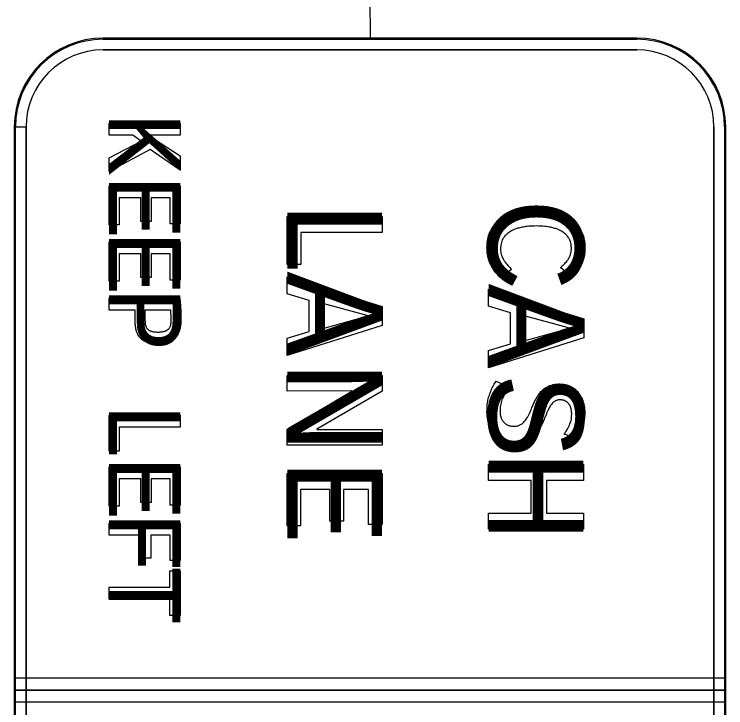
# Model space of a CAD drawing. Extents: x 46672 to 47298, y 5424 to 5829.
# Drawn here: x 46761.54 to 46786.99, y 5574.03 to 5598.84 of the extents above; entities that cross this region are included whole.
import ezdxf

# ---------------------------------------------------------------- set-up
doc = ezdxf.new("R2010")
doc.units = 0
doc.layers.add('LeaderLine_dp', color=7, linetype='Continuous')
doc.layers.add('SignPanel', color=7, linetype='Continuous')

msp = doc.modelspace()

# ---------------------------------------------------------------- linework, layer by layer
at = {"layer": 'LeaderLine_dp'}
msp.add_line((46774.261, 5605.249), (46774.267, 5597.985), dxfattribs=at)
at = {"layer": 'SignPanel'}
for p, q in [((46783.809, 5597.985), (46764.724, 5597.985)), ((46783.809, 5597.985), (46764.724, 5597.985)), ((46783.809, 5597.985), (46764.724, 5597.985)), ((46783.809, 5597.985), (46764.724, 5597.985)), ((46764.724, 5597.943), (46783.809, 5597.943)), ((46783.809, 5597.561), (46764.724, 5597.561)), ((46764.724, 5597.561), (46783.809, 5597.561)), ((46764.724, 5597.561), (46783.809, 5597.561)), ((46761.543, 5594.805), (46761.543, 5552.818)), ((46761.543, 5594.805), (46761.543, 5552.818)), ((46761.543, 5594.805), (46761.968, 5594.805)), ((46761.543, 5594.805), (46761.968, 5594.805)), ((46761.543, 5594.805), (46761.586, 5594.805)), ((46761.543, 5594.804), (46761.543, 5552.818)), ((46761.586, 5594.804), (46761.543, 5594.804)), ((46761.543, 5594.8), (46761.543, 5552.818)), ((46761.968, 5594.8), (46761.543, 5594.8)), ((46761.543, 5594.8), (46761.543, 5552.818)), ((46761.968, 5594.8), (46761.543, 5594.8)), ((46761.586, 5552.818), (46761.586, 5594.804)), ((46761.968, 5594.805), (46761.968, 5552.818)), ((46761.968, 5552.818), (46761.968, 5594.8)), ((46761.968, 5552.818), (46761.968, 5594.8)), ((46786.566, 5552.818), (46786.566, 5594.805)), ((46786.566, 5594.805), (46786.566, 5552.818)), ((46786.566, 5594.805), (46786.566, 5552.818)), ((46786.947, 5594.805), (46786.947, 5552.818)), ((46786.99, 5552.818), (46786.99, 5594.805)), ((46786.99, 5552.818), (46786.99, 5594.805)), ((46786.99, 5552.818), (46786.99, 5594.805)), ((46786.99, 5552.818), (46786.99, 5594.805)), ((46786.99, 5552.818), (46786.99, 5594.805)), ((46761.543, 5575.084), (46761.543, 5574.659)), ((46786.99, 5575.084), (46761.543, 5575.084)), ((46761.543, 5575.084), (46761.543, 5574.659)), ((46786.99, 5575.084), (46761.543, 5575.084)), ((46761.543, 5575.084), (46761.543, 5574.659)), ((46786.99, 5575.084), (46761.543, 5575.084)), ((46786.99, 5574.659), (46786.99, 5575.084)), ((46786.99, 5574.659), (46786.99, 5575.084)), ((46786.99, 5574.659), (46786.99, 5575.084)), ((46761.543, 5574.659), (46786.99, 5574.659)), ((46761.543, 5574.659), (46786.99, 5574.659)), ((46761.543, 5574.659), (46786.99, 5574.659)), ((46761.543, 5574.659), (46761.543, 5574.235)), ((46786.99, 5574.659), (46761.543, 5574.659)), ((46761.543, 5574.659), (46761.543, 5574.235)), ((46786.99, 5574.659), (46761.543, 5574.659)), ((46761.543, 5574.659), (46761.543, 5574.235)), ((46786.99, 5574.659), (46761.543, 5574.659)), ((46786.99, 5574.235), (46786.99, 5574.659)), ((46786.99, 5574.235), (46786.99, 5574.659)), ((46786.99, 5574.235), (46786.99, 5574.659)), ((46761.543, 5574.235), (46786.99, 5574.235)), ((46761.543, 5574.235), (46786.99, 5574.235)), ((46761.543, 5574.235), (46786.99, 5574.235))]:
    msp.add_line(p, q, dxfattribs=at)
for points in [[(46764.936, 5593.706), (46766.084, 5594.294), (46765.786, 5594.516), (46764.936, 5594.513), (46764.936, 5594.943), (46767.481, 5594.943), (46767.481, 5594.513), (46766.356, 5594.516), (46766.356, 5594.5), (46767.481, 5593.774), (46767.481, 5593.264), (46766.399, 5593.994), (46764.936, 5593.215), (46764.936, 5593.706)], [(46764.936, 5592.704), (46767.481, 5592.704), (46767.481, 5591.337), (46767.116, 5591.337), (46767.116, 5592.274), (46766.445, 5592.274), (46766.445, 5591.427), (46766.077, 5591.427), (46766.077, 5592.274), (46765.295, 5592.274), (46765.295, 5591.303), (46764.936, 5591.303), (46764.936, 5592.704)], [(46771.306, 5591.598), (46774.699, 5591.598), (46774.699, 5591.025), (46771.793, 5591.025), (46771.793, 5589.883), (46771.306, 5589.883), (46771.306, 5591.598)], [(46764.936, 5590.691), (46767.481, 5590.691), (46767.481, 5589.324), (46767.116, 5589.324), (46767.116, 5590.261), (46766.445, 5590.261), (46766.445, 5589.414), (46766.077, 5589.414), (46766.077, 5590.261), (46765.295, 5590.261), (46765.295, 5589.29), (46764.936, 5589.29), (46764.936, 5590.691)], [(46779.333, 5589.71), (46778.937, 5589.408)], [(46781.478, 5589.428), (46781.081, 5589.774)], [(46771.306, 5587.245), (46772.094, 5587.482), (46772.094, 5588.601), (46771.306, 5588.832), (46771.306, 5589.439), (46774.707, 5588.387), (46774.707, 5587.699), (46771.306, 5586.628), (46771.306, 5587.245)], [(46778.508, 5586.804), (46779.295, 5587.041), (46779.295, 5588.16), (46778.508, 5588.391), (46778.508, 5588.998), (46781.909, 5587.946), (46781.909, 5587.258), (46778.508, 5586.187), (46778.508, 5586.804)], [(46765.87, 5587.848), (46765.87, 5588.248), (46764.936, 5588.248), (46764.936, 5588.678), (46767.465, 5588.678)], [(46774.168, 5588.035), (46774.168, 5588.055), (46772.58, 5588.493), (46772.58, 5587.594), (46774.168, 5588.035)], [(46767.138, 5588.248), (46766.219, 5588.248), (46766.219, 5587.912)], [(46781.37, 5587.594), (46781.37, 5587.614), (46779.782, 5588.052), (46779.782, 5587.153), (46781.37, 5587.594)], [(46771.306, 5583.978), (46773.62, 5585.35), (46773.62, 5585.361), (46771.306, 5585.355), (46771.306, 5585.915), (46774.699, 5585.915), (46774.699, 5585.35), (46772.365, 5583.99), (46772.365, 5583.978), (46774.699, 5583.978), (46774.699, 5583.425), (46771.306, 5583.425), (46771.306, 5583.978)], [(46778.78, 5585.711), (46779.248, 5585.501)], [(46764.936, 5584.49), (46767.481, 5584.49), (46767.481, 5584.06), (46765.301, 5584.06), (46765.301, 5583.203), (46764.936, 5583.203), (46764.936, 5584.49)], [(46781.682, 5583.649), (46781.207, 5583.816)], [(46778.508, 5580.99), (46780.029, 5580.99), (46780.029, 5582.153), (46778.508, 5582.153), (46778.508, 5582.726), (46781.901, 5582.726), (46781.901, 5582.153), (46780.573, 5582.153), (46780.573, 5580.99), (46781.901, 5580.99), (46781.901, 5580.417), (46778.508, 5580.417), (46778.508, 5580.99)], [(46764.936, 5582.642), (46767.481, 5582.642), (46767.481, 5581.276), (46767.116, 5581.276), (46767.116, 5582.212), (46766.445, 5582.212), (46766.445, 5581.365), (46766.077, 5581.365), (46766.077, 5582.212), (46765.295, 5582.212), (46765.295, 5581.242), (46764.936, 5581.242), (46764.936, 5582.642)], [(46771.306, 5582.407), (46774.699, 5582.407), (46774.699, 5580.585), (46774.213, 5580.585), (46774.213, 5581.834), (46773.318, 5581.834), (46773.318, 5580.704), (46772.827, 5580.704), (46772.827, 5581.834), (46771.784, 5581.834), (46771.784, 5580.539), (46771.306, 5580.539), (46771.306, 5582.407)], [(46767.116, 5580.2), (46766.433, 5580.2), (46766.433, 5579.377), (46766.065, 5579.377), (46766.065, 5580.2), (46764.936, 5580.2), (46764.936, 5580.629), (46767.481, 5580.629), (46767.481, 5579.291), (46767.116, 5579.291), (46767.116, 5580.2)], [(46767.11, 5577.912), (46764.936, 5577.912), (46764.936, 5578.341), (46767.11, 5578.341), (46767.11, 5578.929), (46767.481, 5578.929), (46767.481, 5577.322), (46767.11, 5577.322), (46767.11, 5577.912)]]:
    msp.add_lwpolyline(points, dxfattribs=at)
for centre, radius, start, end in [((46764.724, 5594.805), 3.181, 90, 180), ((46764.724, 5594.805), 3.181, 90, 180), ((46764.724, 5594.805), 3.181, 90, 180), ((46764.724, 5594.805), 3.181, 90, 180), ((46764.724, 5594.805), 3.181, 90, 180), ((46783.809, 5594.805), 3.181, 0, 90), ((46783.809, 5594.805), 3.181, 0, 90), ((46783.809, 5594.805), 3.181, 0, 90), ((46783.809, 5594.805), 3.181, 0, 90), ((46783.809, 5594.805), 3.181, 0, 90), ((46764.724, 5594.805), 3.138, 90, 180), ((46783.809, 5594.805), 3.138, 0, 90), ((46764.724, 5594.805), 2.757, 90, 180), ((46764.724, 5594.805), 2.757, 90, 180), ((46764.724, 5594.805), 2.757, 90, 180), ((46783.809, 5594.805), 2.757, 0, 90), ((46783.809, 5594.805), 2.757, 0, 90), ((46783.809, 5594.805), 2.757, 0, 90)]:
    msp.add_arc(centre, radius, start, end, dxfattribs=at)
for points in [[(46778.45, 5590.476), (46778.451, 5590.506), (46778.452, 5590.594), (46778.466, 5590.735), (46778.499, 5590.894), (46778.542, 5591.017), (46778.585, 5591.107), (46778.632, 5591.192), (46778.699, 5591.291), (46778.793, 5591.398), (46778.882, 5591.478), (46778.959, 5591.535), (46779.104, 5591.631), (46779.292, 5591.717), (46779.519, 5591.781), (46779.74, 5591.826), (46779.972, 5591.853), (46780.15, 5591.856), (46780.211, 5591.856)], [(46780.211, 5591.856), (46780.267, 5591.855), (46780.433, 5591.853), (46780.652, 5591.826), (46780.865, 5591.781), (46781.066, 5591.723), (46781.254, 5591.64), (46781.404, 5591.548), (46781.502, 5591.476), (46781.594, 5591.395), (46781.691, 5591.287), (46781.761, 5591.187), (46781.811, 5591.102), (46781.857, 5591.011), (46781.902, 5590.888), (46781.938, 5590.727), (46781.953, 5590.585), (46781.954, 5590.497), (46781.954, 5590.466)], [(46780.211, 5591.263), (46780.136, 5591.261), (46779.985, 5591.257), (46779.798, 5591.235), (46779.616, 5591.201), (46779.478, 5591.159), (46779.365, 5591.109), (46779.291, 5591.069), (46779.222, 5591.024), (46779.147, 5590.963), (46779.091, 5590.904), (46779.051, 5590.854), (46779.015, 5590.801), (46778.978, 5590.726), (46778.95, 5590.626), (46778.938, 5590.535), (46778.937, 5590.479), (46778.937, 5590.459)], [(46781.468, 5590.466), (46781.468, 5590.482), (46781.467, 5590.53), (46781.458, 5590.608), (46781.436, 5590.697), (46781.409, 5590.766), (46781.382, 5590.817), (46781.352, 5590.866), (46781.307, 5590.924), (46781.244, 5590.987), (46781.185, 5591.033), (46781.119, 5591.076), (46781.014, 5591.131), (46780.88, 5591.18), (46780.734, 5591.215), (46780.523, 5591.253), (46780.346, 5591.259), (46780.211, 5591.263)], [(46778.937, 5589.408), (46778.901, 5589.444), (46778.794, 5589.55), (46778.675, 5589.711), (46778.591, 5589.862), (46778.539, 5589.973), (46778.498, 5590.091), (46778.466, 5590.24), (46778.452, 5590.37), (46778.451, 5590.449), (46778.45, 5590.476)], [(46778.937, 5590.459), (46778.937, 5590.441), (46778.938, 5590.387), (46778.949, 5590.299), (46778.974, 5590.199), (46779.006, 5590.121), (46779.047, 5590.046), (46779.117, 5589.939), (46779.217, 5589.821), (46779.303, 5589.739), (46779.333, 5589.71)], [(46781.081, 5589.774), (46781.111, 5589.801), (46781.167, 5589.852), (46781.233, 5589.919), (46781.292, 5589.984), (46781.333, 5590.038), (46781.368, 5590.092), (46781.399, 5590.148), (46781.424, 5590.206), (46781.443, 5590.266), (46781.458, 5590.33), (46781.467, 5590.397), (46781.468, 5590.448), (46781.468, 5590.466)], [(46781.954, 5590.466), (46781.954, 5590.44), (46781.953, 5590.365), (46781.941, 5590.243), (46781.911, 5590.103), (46781.874, 5589.993), (46781.826, 5589.888), (46781.744, 5589.74), (46781.623, 5589.578), (46781.516, 5589.467), (46781.478, 5589.428)], [(46767.465, 5588.678), (46767.471, 5588.621), (46767.484, 5588.503), (46767.496, 5588.322), (46767.504, 5588.132), (46767.505, 5588.002), (46767.505, 5587.935)], [(46767.159, 5587.917), (46767.159, 5587.943), (46767.158, 5587.995), (46767.152, 5588.075), (46767.145, 5588.16), (46767.14, 5588.218), (46767.138, 5588.248)], [(46766.694, 5587.033), (46766.661, 5587.034), (46766.569, 5587.035), (46766.436, 5587.053), (46766.314, 5587.087), (46766.23, 5587.123), (46766.165, 5587.159), (46766.116, 5587.195), (46766.079, 5587.226), (46766.045, 5587.26), (46766.007, 5587.307), (46765.967, 5587.371), (46765.928, 5587.455), (46765.891, 5587.579), (46765.872, 5587.717), (46765.87, 5587.814), (46765.87, 5587.848)], [(46766.219, 5587.912), (46766.219, 5587.894), (46766.22, 5587.842), (46766.226, 5587.776), (46766.236, 5587.722), (46766.245, 5587.688), (46766.256, 5587.657), (46766.274, 5587.622), (46766.293, 5587.596), (46766.31, 5587.577), (46766.328, 5587.559), (46766.354, 5587.539), (46766.39, 5587.519), (46766.424, 5587.505), (46766.461, 5587.493), (46766.523, 5587.478), (46766.602, 5587.47), (46766.665, 5587.469), (46766.688, 5587.469)], [(46766.688, 5587.469), (46766.709, 5587.469), (46766.767, 5587.47), (46766.842, 5587.477), (46766.901, 5587.49), (46766.938, 5587.5), (46766.971, 5587.512), (46767.008, 5587.532), (46767.035, 5587.551), (46767.055, 5587.568), (46767.073, 5587.587), (46767.093, 5587.613), (46767.113, 5587.648), (46767.127, 5587.68), (46767.138, 5587.715), (46767.15, 5587.772), (46767.158, 5587.842), (46767.159, 5587.897), (46767.159, 5587.917)], [(46767.505, 5587.935), (46767.505, 5587.902), (46767.504, 5587.807), (46767.49, 5587.684), (46767.466, 5587.568), (46767.446, 5587.5), (46767.423, 5587.436), (46767.395, 5587.377), (46767.361, 5587.322), (46767.33, 5587.281), (46767.298, 5587.243), (46767.251, 5587.199), (46767.189, 5587.152), (46767.13, 5587.12), (46767.08, 5587.098), (46767.026, 5587.077), (46766.935, 5587.052), (46766.818, 5587.036), (46766.731, 5587.034), (46766.694, 5587.033)], [(46778.45, 5584.63), (46778.451, 5584.682), (46778.454, 5584.834), (46778.482, 5585.03), (46778.533, 5585.213), (46778.598, 5585.385), (46778.679, 5585.553), (46778.754, 5585.671), (46778.78, 5585.711)], [(46779.248, 5585.501), (46779.226, 5585.47), (46779.158, 5585.378), (46779.08, 5585.246), (46779.02, 5585.127), (46778.982, 5585.039), (46778.952, 5584.948), (46778.928, 5584.834), (46778.917, 5584.736), (46778.916, 5584.677), (46778.916, 5584.657)], [(46780.039, 5584.724), (46780.062, 5584.777), (46780.108, 5584.883), (46780.168, 5585.014), (46780.233, 5585.141), (46780.295, 5585.236), (46780.357, 5585.313), (46780.404, 5585.365), (46780.466, 5585.422), (46780.547, 5585.481), (46780.623, 5585.523), (46780.692, 5585.554), (46780.787, 5585.584), (46780.908, 5585.603), (46780.998, 5585.605), (46781.037, 5585.606)], [(46781.037, 5585.606), (46781.056, 5585.606), (46781.112, 5585.605), (46781.202, 5585.596), (46781.304, 5585.575), (46781.383, 5585.547), (46781.442, 5585.52), (46781.498, 5585.49), (46781.563, 5585.449), (46781.634, 5585.391), (46781.687, 5585.337), (46781.736, 5585.279), (46781.797, 5585.192), (46781.853, 5585.082), (46781.893, 5584.963), (46781.925, 5584.839), (46781.944, 5584.709), (46781.946, 5584.612), (46781.946, 5584.579)], [(46781.06, 5585.041), (46781.052, 5585.041), (46781.026, 5585.041), (46780.984, 5585.035), (46780.937, 5585.023), (46780.901, 5585.007), (46780.867, 5584.987), (46780.822, 5584.954), (46780.776, 5584.908), (46780.735, 5584.855), (46780.694, 5584.795), (46780.658, 5584.729), (46780.616, 5584.639), (46780.575, 5584.541), (46780.542, 5584.462), (46780.525, 5584.421)], [(46781.48, 5584.53), (46781.48, 5584.547), (46781.479, 5584.598), (46781.471, 5584.664), (46781.457, 5584.728), (46781.442, 5584.78), (46781.421, 5584.829), (46781.399, 5584.867), (46781.382, 5584.891), (46781.365, 5584.913), (46781.341, 5584.939), (46781.308, 5584.967), (46781.278, 5584.987), (46781.252, 5585.001), (46781.224, 5585.014), (46781.187, 5585.027), (46781.139, 5585.037), (46781.096, 5585.041), (46781.07, 5585.041), (46781.06, 5585.041)], [(46779.481, 5583.541), (46779.438, 5583.542), (46779.335, 5583.544), (46779.197, 5583.565), (46779.087, 5583.596), (46779.02, 5583.622), (46778.958, 5583.65), (46778.884, 5583.69), (46778.803, 5583.747), (46778.743, 5583.801), (46778.699, 5583.848), (46778.658, 5583.897), (46778.612, 5583.963), (46778.564, 5584.05), (46778.532, 5584.127), (46778.505, 5584.209), (46778.474, 5584.331), (46778.453, 5584.478), (46778.451, 5584.591), (46778.45, 5584.63)], [(46778.916, 5584.657), (46778.916, 5584.639), (46778.917, 5584.586), (46778.926, 5584.516), (46778.941, 5584.448), (46778.958, 5584.392), (46778.981, 5584.339), (46779.007, 5584.296), (46779.026, 5584.27), (46779.046, 5584.245), (46779.075, 5584.215), (46779.114, 5584.183), (46779.151, 5584.161), (46779.182, 5584.144), (46779.215, 5584.129), (46779.261, 5584.114), (46779.331, 5584.1), (46779.384, 5584.098), (46779.417, 5584.097)], [(46779.417, 5584.097), (46779.427, 5584.097), (46779.459, 5584.098), (46779.509, 5584.103), (46779.566, 5584.116), (46779.61, 5584.133), (46779.65, 5584.154), (46779.702, 5584.187), (46779.758, 5584.234), (46779.806, 5584.289), (46779.853, 5584.35), (46779.896, 5584.417), (46779.943, 5584.508), (46779.988, 5584.605), (46780.022, 5584.684), (46780.039, 5584.724)], [(46781.207, 5583.816), (46781.228, 5583.844), (46781.287, 5583.926), (46781.354, 5584.041), (46781.402, 5584.143), (46781.431, 5584.215), (46781.458, 5584.305), (46781.477, 5584.416), (46781.479, 5584.497), (46781.48, 5584.53)], [(46781.946, 5584.579), (46781.945, 5584.535), (46781.943, 5584.41), (46781.92, 5584.247), (46781.88, 5584.092), (46781.828, 5583.941), (46781.763, 5583.793), (46781.702, 5583.686), (46781.682, 5583.649)], [(46780.525, 5584.421), (46780.503, 5584.369), (46780.458, 5584.264), (46780.396, 5584.135), (46780.326, 5584.008), (46780.259, 5583.913), (46780.184, 5583.826), (46780.1, 5583.744), (46780.002, 5583.675), (46779.909, 5583.626), (46779.836, 5583.594), (46779.738, 5583.564), (46779.613, 5583.544), (46779.52, 5583.542), (46779.481, 5583.541)]]:
    msp.add_open_spline(points, degree=3, dxfattribs=at)

# ---------------------------------------------------------------- texts
for s, height, p in [('K', 2.545, (46764.936, 5595.323)), ('K', 2.545, (46764.936, 5595.323)), ('E', 2.545, (46764.936, 5593.084)), ('E', 2.545, (46764.936, 5593.084)), ('C', 3.393, (46778.508, 5592.227)), ('C', 3.393, (46778.508, 5592.227)), ('L', 3.393, (46771.306, 5592.105)), ('L', 3.393, (46771.306, 5592.105)), ('E', 2.545, (46764.936, 5591.071)), ('E', 2.545, (46764.936, 5591.071)), ('A', 3.393, (46771.306, 5589.642)), ('A', 3.393, (46771.306, 5589.642)), ('A', 3.393, (46778.508, 5589.201)), ('A', 3.393, (46778.508, 5589.201)), ('P', 2.545, (46764.936, 5589.058)), ('P', 2.545, (46764.936, 5589.058)), ('N', 3.393, (46771.306, 5586.422)), ('N', 3.393, (46771.306, 5586.422)), ('S', 3.393, (46778.508, 5585.981)), ('S', 3.393, (46778.508, 5585.981)), ('L', 2.545, (46764.936, 5584.87)), ('L', 2.545, (46764.936, 5584.87)), ('E', 2.545, (46764.936, 5583.022)), ('E', 2.545, (46764.936, 5583.022)), ('H', 3.393, (46778.508, 5583.233)), ('H', 3.393, (46778.508, 5583.233)), ('E', 3.393, (46771.306, 5582.914)), ('E', 3.393, (46771.306, 5582.914)), ('F', 2.545, (46764.936, 5581.01)), ('F', 2.545, (46764.936, 5581.01)), ('T', 2.545, (46764.936, 5579.083)), ('T', 2.545, (46764.936, 5579.083))]:
    msp.add_text(s, height=height, rotation=270, dxfattribs=at).set_placement(p)

doc.saveas('drawing.dxf')
